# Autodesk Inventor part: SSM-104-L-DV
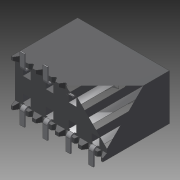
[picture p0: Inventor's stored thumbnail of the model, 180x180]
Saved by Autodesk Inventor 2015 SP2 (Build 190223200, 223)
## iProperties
Created: 2014-11
Part Number: SSM-104-L-DV
Material: Allgemein
Document SubType Name: Modeling
Designer: rYan
Density: 1 g/cm^3
Appearance: Vorgabe
Author: rYan
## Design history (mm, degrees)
node "Samtec-SSM-104-L-DV.sat1"
node "Volumenkörper1"
node "Basis1"
